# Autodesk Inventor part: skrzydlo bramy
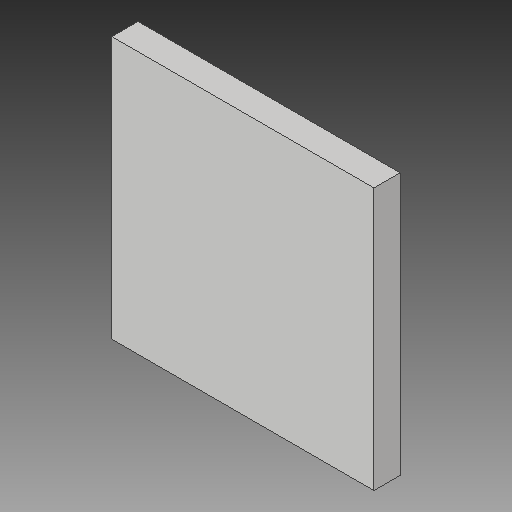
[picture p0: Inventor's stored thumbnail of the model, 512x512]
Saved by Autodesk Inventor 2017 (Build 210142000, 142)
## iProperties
Created: 2020-09
Part Number: skrzydlo bramy
Material: Generic
Document SubType Name: Modeling
Designer: X
Density: 1 g/cm^3
Appearance: Default
Mass: 6.4 g
Surface Area: 38.4 cm^2
Volume: 6.4 cm^3
Author: X
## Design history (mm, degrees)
sketch "Szkic1"
  geometry: L1 (0, 0)-(1140, 0); L2 (1140, 0)-(1140, 1940); L3 (1140, 1940)-(0, 1940); L4 (0, 1940)-(0, 0); L5 (0, 1450)-(1140, 1450); L6 (0, 970)-(1140, 970); L7 (0, 480)-(1140, 480); L8 (1140, 0)-(1180, 0); L9 (1180, 0)-(1180, -40); L10 (1180, -40)-(1140, -40); L11 (1140, -40)-(1140, 0); L12 (1140, 1940)-(1180, 1940); L13 (1180, 1940)-(1180, 1980); L14 (1180, 1980)-(1140, 1980); L15 (1140, 1980)-(1140, 1940)
  constraints: 30 end point, 6 parallel, 5 perpendicular, 5 point on line, 3 horizontal, 2 midpoint
  dimensions: "d0" = 1140 distance of L2.end L3.end; "d1" = 1940 distance of L1.start L3.end; "d8" = 480 distance of L6.end L5.end
extrude "Wyciągnięcie proste1" new body sketch "Szkic1" distance "d9" = 4; taper "d10" = 0 deg
node "Bryła1"
